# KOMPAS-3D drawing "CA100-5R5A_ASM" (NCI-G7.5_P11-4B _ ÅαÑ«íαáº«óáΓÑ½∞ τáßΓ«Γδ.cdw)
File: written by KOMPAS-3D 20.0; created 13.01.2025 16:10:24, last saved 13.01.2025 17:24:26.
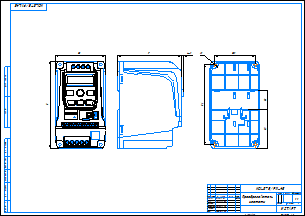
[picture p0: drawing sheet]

Sheet 1: A2, landscape

Document properties: Автор: admin; Полное имя файла: P:\INSTART\Технический отдел\ОР\Прочие задачи\КД на номенклатурный ряд\КД на типоразмеры ПЧ\NCI\NCI-G7.5_P11-4B\NCI-G7.5_P11-4B _ Преобразователь частоты.cdw

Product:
- Part/product: CA100-5R5A_ASM
    Масса: 7.13181
    Комментарий: NOT SPECIFIED
  - Component [detail]: AA  | Масса: 1.44663; source file: C:\Уралов Работа\Уралов (локальная)\ПЧ\! Китай 3Д-модель NCI\NCI 4.0-7.5 4B\AA.m3d
  - Component [detail]: CA100-2R2A-SJ-04  | Масса: 0.00516082; source file: C:\Уралов Работа\Уралов (локальная)\ПЧ\! Китай 3Д-модель NCI\NCI 4.0-7.5 4B\CA100-2R2A-SJ-04.m3d
  - Component [assembly]: JIANPAN99_ASM_ASM  | Масса: 0.107178; Комментарий: NOT SPECIFIED; source file: C:\Уралов Работа\Уралов (локальная)\ПЧ\! Китай 3Д-модель NCI\NCI 4.0-7.5 4B\JIANPAN99_ASM_ASM.a3d
  - Component [assembly]: CA100-5R5A-SJ_ASM  | Масса: 1.6976; Комментарий: NOT SPECIFIED; source file: C:\Уралов Работа\Уралов (локальная)\ПЧ\! Китай 3Д-модель NCI\NCI 4.0-7.5 4B\CA100-5R5A-SJ_ASM.a3d
  - Component [assembly]: PCB_ASM  | Масса: 1.9346; source file: C:\Уралов Работа\Уралов (локальная)\ПЧ\! Китай 3Д-модель NCI\NCI 4.0-7.5 4B\PCB_ASM.a3d
  - Component [assembly]: QJ_ASM  | Масса: 0.208727; source file: C:\Уралов Работа\Уралов (локальная)\ПЧ\! Китай 3Д-модель NCI\NCI 4.0-7.5 4B\QJ_ASM.a3d
  - Component [detail]: CA100-4R0A-SR-01  | Масса: 0.923365; source file: C:\Уралов Работа\Уралов (локальная)\ПЧ\! Китай 3Д-модель NCI\NCI 4.0-7.5 4B\CA100-4R0A-SR-01.m3d
  - Component [detail]: CA100-5R5A-SR-01  | Масса: 0.808548; source file: C:\Уралов Работа\Уралов (локальная)\ПЧ\! Китай 3Д-модель NCI\NCI 4.0-7.5 4B\CA100-5R5A-SR-01.m3d

Title block, sheet 1: Наименование: Преобразователь / частоты; designation: NCI-G7.5/P11-4B; Количество листов документа: 1; organisation: INSTART; cell 10: Согласовано; Форматы листов документа: A2; stored path: P:\INSTART\Технический отдел\ОР\Прочие задачи\КД на номенклатурный ряд\КД на типоразмеры ПЧ\NCI\NCI-G4.0_P5.5-4B\NCI-G4.0_P5.5-4B _ Преобразователь частоты.cdw; Разработал: Уралов Д.А.; Проверил: Андреев Н.В.; Подписал: Смелков Ж.Е.; Утвердил: Ефремов И.Н.; Разработал, date: 13.01.25

Views: Вид 1, Проекционный вид 2
Referenced files in C:\Уралов Работа\Уралов (локальная)\ПЧ\! Китай 3Д-модель NCI\NCI 4.0-7.5 4B\: CA100-4R0A-SR-01.m3d, CA100-5R5A-SR-01.m3d, 6025.m3d, QJ_ASM.a3d, QDB.m3d, DRI.m3d, 6912184100XX_MASS.m3d, 6912184100XX_PIN.m3d, 6912184100XX_VIS.m3d, 691218410003.m3d, ASSEM1_ASM.a3d, EU5-03-952_ASM.a3d, QDB_ASM.a3d, 2R2-CM.m3d, EU1_5-14-5_08-00_1_.m3d, LED.m3d, DWQ_2.m3d, ANJIAN.m3d, BM.m3d, 485.m3d, 2R2-CM_ASM.a3d, DRB.m3d, DR.m3d, DRB_ASM.a3d, PCB_ASM.a3d, CA100-5R5A-SJ-01.m3d, CA100-5R5A-SJ-02.m3d, CA100-5R5A-SJ-01-.m3d, CA100-5R5A-SJ_ASM.a3d, CA100-2R2A-SJ-05_45.m3d, CA100-2R2A-SJ-06_23.m3d, CA100-2R2A-SJ-03_22.m3d, JIANPAN99_ASM_17_ASM.a3d, JIANPAN99_ASM_ASM.a3d, CA100-2R2A-SJ-04.m3d, AA.m3d, NCI 4.0-7.5 4B.a3d
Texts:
  CA100-4R0A-SR-01
  CA100-4R0A-SR-01 CA100-4R0A-SR-01
  CA100-5R5A-SR-01
  CA100-5R5A-SR-01 CA100-5R5A-SR-01
  QJ_ASM QJ_ASM
  QDB
  QDB QDB
  DRI
  DRI DRI
  6912184100XX_MASS 6912184100XX_MASS
  6912184100XX_PIN 6912184100XX_PIN
  6912184100XX_VIS 6912184100XX_VIS
  ASSEM1_ASM ASSEM1_ASM
  EU5-03-952_ASM
  EU5-03-952_ASM EU5-03-952_ASM
  QDB_ASM QDB_ASM
  EU1_5-14-5_08-00_1_
  EU1_5-14-5_08-00_1_ EU1_5-14-5_08-00_1_
  LED
  LED LED
  DWQ_2 DWQ_2
  ANJIAN
  ANJIAN ANJIAN
  BM BM
  DRB
  DRB DRB
  DR DR
  DRB_ASM DRB_ASM
  PCB_ASM PCB_ASM
  CA100-5R5A-SJ-01
  CA100-5R5A-SJ-01 CA100-5R5A-SJ-01
  CA100-5R5A-SJ-02
  CA100-5R5A-SJ-02 CA100-5R5A-SJ-02
  CA100-5R5A-SJ-01-
  CA100-5R5A-SJ-01- CA100-5R5A-SJ-01-
  CA100-5R5A-SJ_ASM
  CA100-5R5A-SJ_ASM CA100-5R5A-SJ_ASM
  CA100-2R2A-SJ-05_45
  CA100-2R2A-SJ-05_45 CA100-2R2A-SJ-05_45
  CA100-2R2A-SJ-06_23
  CA100-2R2A-SJ-06_23 CA100-2R2A-SJ-06_23
  CA100-2R2A-SJ-03_22
  CA100-2R2A-SJ-03_22 CA100-2R2A-SJ-03_22
  JIANPAN99_ASM_17_ASM JIANPAN99_ASM_17_ASM
  JIANPAN99_ASM_ASM JIANPAN99_ASM_ASM
  Поверхности
  CA100-2R2A-SJ-04
  CA100-2R2A-SJ-04 CA100-2R2A-SJ-04
  AA AA
  CA100-5R5A_ASM
  CA100-5R5A_ASM CA100-5R5A_ASM
Dimensions and other numbers on the sheet: 4±1; 1:1; 1; 13.01.25; 6025; 6025 6025; 2R2-CM; 2R2-CM 2R2-CM; 485; 485 485; 2R2-CM_ASM; 2R2-CM_ASM 2R2-CM_ASM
